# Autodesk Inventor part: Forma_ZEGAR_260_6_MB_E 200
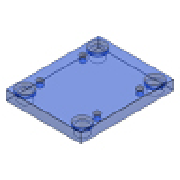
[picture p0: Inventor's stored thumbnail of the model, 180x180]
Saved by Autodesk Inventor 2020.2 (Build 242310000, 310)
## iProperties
Manager: www.cadconsulting.pl
Company: Fabian Stasiak CAD Consulting
Created: 2014-02
Part Number: Forma_ZEGAR_260_6_MB_E 200
Material: S 55 C
Description: Cavity Plate
Document SubType Name: Modeling
Designer: F.Stasiak
Standard Revision: 1
Manufacturer: DME
Language: pl-PL
Size Designation: 496x346x66
Categories: <MemberInstance><Categories><Category DisplayName="Forma wtryskowa" InternalName="349578f2-f4d4-4954-8c09-8e99297a61c0" Mnemonic="MOLD"><Category DisplayName="P
Density: 7.85 g/cm^3
Appearance: Clear - Blue
Catalog Web Link: www.expertbooks.pl
IsCustomPart: 1
Author: F.Stasiak
Subject: Zbiór ćwiczeń. Autodesk Inventor 2020. Kurs Professional
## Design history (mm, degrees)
sketch "Sketch1"
  geometry: L1 (-173, 248)-(173, 248); L2 (173, 248)-(173, -248); L3 (173, -248)-(-173, -248); L4 (-173, -248)-(-173, 248); 3 further points
  constraints: 8 end point, 2 midpoint, 2 parallel, 1 horizontal, 1 horizontal alignment, 1 perpendicular, 1 vertical alignment
  dimensions: "d126" = 346 distance between parallel lines of L2 L4 (= W_); "d127" = 496 distance between parallel lines of L3 L1 (= L)
extrude "Extrusion1" new body sketch "Sketch1" distance "d20" = 66 (= H_); taper "d30" = 0 deg
sketch "Sketch2"
  geometry: 3 further points
  dimensions: "d128" = 137 horizontal distance of point (0, 0) point (-137, 165) (= 0.5 x S1_W); "d129" = 165 vertical distance of point (0, 0) point (-137, 165) (= 0.5 x S1_L); "d130" = 208 vertical distance of point (0, 0) point (-137, 208) (= 0.5 x GP_L); "d131" = 137 horizontal distance of point (0, 0) point (-137, 208) (= 0.5 x GP_W)
hole "Hole1" sketch "Sketch2" diameter "d132" = 42 (= GP_d1); stored, may be unused: countersink angle "d136" = 90 deg, drill point angle "d138" = 0 deg; dims "d133" = 6, "d134" = 48 (= GP_d2), "d135" = 6 (= GP_k), "d137" = 66 (= H_)
pattern_linear "Rectangular Pattern1" dims "d148" = 416 (computed from GP_L, Nl), "d151" = 274 (computed from GP_W, Nw)
hole "Hole2" sketch "Sketch2" diameter "d139" = 13.835; stored, may be unused: countersink angle "d143" = 90 deg, drill point angle "d145" = 118 deg; dims "d140" = 24.5 (= H_l), "d141" = 48 (= GP_d2), "d142" = 6 (= GP_k), "d144" = 25 (= H_u)
pattern_linear "Rectangular Pattern2" dims "d154" = 330 (computed from S1_L, Ns), "d157" = 274 (computed from S1_W, Nw)
chamfer "Chamfer1" distance "d158" = 0.5; stored, may be unused: second distance "d159" = 2, angle "d160" = 45 deg
sketch "Szkic3"
  geometry: L1 (-78, -154.488)-(-78, 154.488); L2 (72.488, -160)-(-72.488, -160); L3 (78, 154.488)-(78, -154.488); L4 (-72.488, 160)-(72.488, 160); A1 r 4 centre (-75.879, 157.879) between (-72.488, 160) and (-78, 154.488); A2 r 4 centre (-75.879, -157.879) between (-78, -154.488) and (-72.488, -160); A3 r 4 centre (75.879, -157.879) between (72.488, -160) and (78, -154.488); A4 r 4 centre (75.879, 157.879) between (78, 154.488) and (72.488, 160)
  constraints: 8 end point, 8 point on circle, 4 centre point
extrude "Wyciągnięcie proste2" cut sketch "Szkic3" distance "d162" = 60; taper "d163" = 0 deg
node "Płaszczyzna konstrukcyjna2"
node "Płaszczyzna konstrukcyjna3"
node "Płaszczyzna konstrukcyjna4"
node "Płaszczyzna konstrukcyjna5"
node "Płaszczyzna konstrukcyjna6"
node "Płaszczyzna konstrukcyjna7"
node "Płaszczyzna konstrukcyjna8"
node "Płaszczyzna konstrukcyjna9"
feature "Rzeźbienie9"
feature "Rzeźbienie10"
feature "Rzeźbienie11"
feature "Rzeźbienie12"
feature "Rzeźbienie13"
feature "Rzeźbienie14"
feature "Rzeźbienie15"
feature "Rzeźbienie16"
feature "Rzeźbienie17"
feature "Rzeźbienie18"
feature "Rzeźbienie19"
feature "Rzeźbienie33"
feature "Gwint2" dims "d166" = 0, "d167" = 0
feature "Rzeźbienie34"
feature "Rzeźbienie36"
feature "Gwint4" dims "d170" = 0, "d171" = 0
feature "Rzeźbienie37"
feature "Gwint5" dims "d172" = 0, "d173" = 0
feature "Rzeźbienie38"
feature "Gwint6" dims "d174" = 0, "d175" = 0
feature "Rzeźbienie39"
feature "Gwint7" dims "d176" = 0, "d177" = 0
feature "Rzeźbienie40"
feature "Gwint8" dims "d178" = 0, "d179" = 0
feature "Rzeźbienie41"
feature "Gwint9" dims "d180" = 0, "d181" = 0
feature "Rzeźbienie42"
feature "Gwint10" dims "d182" = 0, "d183" = 0
feature "Rzeźbienie43"
feature "Gwint11" dims "d184" = 0, "d185" = 0
feature "Rzeźbienie44"
feature "Gwint12" dims "d186" = 0, "d187" = 0
feature "Rzeźbienie45"
feature "Gwint13" dims "d188" = 0, "d189" = 0
feature "Rzeźbienie46"
feature "Gwint14" dims "d190" = 0, "d191" = 0
feature "Rzeźbienie47"
feature "Rzeźbienie48"
feature "Rzeźbienie49"
feature "Rzeźbienie50"
feature "Rzeźbienie51"
feature "Rzeźbienie52"
feature "Rzeźbienie54"
feature "Rzeźbienie55"
feature "Rzeźbienie56"
feature "Rzeźbienie57"
feature "Rzeźbienie58"
feature "Rzeźbienie59"
feature "Rzeźbienie60"
feature "Rzeźbienie61"
feature "Rzeźbienie62"
feature "Rzeźbienie63"
feature "Rzeźbienie64"
feature "Rzeźbienie65"
feature "Rzeźbienie66"
feature "Rzeźbienie67"
feature "Rzeźbienie68"
feature "Rzeźbienie69"
feature "Rzeźbienie70"
body "Solid1"
feature "Powierzchnia9"
body "Srf9"
feature "Powierzchnia10"
body "Srf10"
feature "Powierzchnia11"
body "Srf11"
feature "Powierzchnia12"
body "Srf12"
feature "Powierzchnia13"
body "Srf13"
feature "Powierzchnia14"
body "Srf14"
feature "Powierzchnia15"
body "Srf15"
feature "Powierzchnia16"
body "Srf16"
feature "Powierzchnia17"
body "Srf17"
feature "Powierzchnia18"
body "Srf18"
feature "Powierzchnia19"
body "Srf19"
feature "Powierzchnia33"
body "Srf33"
feature "Powierzchnia34"
body "Srf34"
feature "Powierzchnia36"
body "Srf36"
feature "Powierzchnia37"
body "Srf37"
feature "Powierzchnia38"
body "Srf38"
feature "Powierzchnia39"
body "Srf39"
feature "Powierzchnia40"
body "Srf40"
feature "Powierzchnia41"
body "Srf41"
feature "Powierzchnia42"
body "Srf42"
feature "Powierzchnia43"
body "Srf43"
feature "Powierzchnia44"
body "Srf44"
feature "Powierzchnia45"
body "Srf45"
feature "Powierzchnia46"
body "Srf46"
feature "Powierzchnia47"
body "Srf47"
feature "Powierzchnia48"
body "Srf48"
feature "Powierzchnia49"
body "Srf49"
feature "Powierzchnia50"
body "Srf50"
feature "Powierzchnia51"
body "Srf51"
feature "Powierzchnia52"
body "Srf52"
feature "Powierzchnia54"
body "Srf54"
feature "Powierzchnia55"
body "Srf55"
feature "Powierzchnia56"
body "Srf56"
feature "Powierzchnia57"
body "Srf57"
feature "Powierzchnia58"
body "Srf58"
feature "Powierzchnia59"
body "Srf59"
feature "Powierzchnia60"
body "Srf60"
feature "Powierzchnia61"
body "Srf61"
feature "Powierzchnia62"
body "Srf62"
feature "Powierzchnia63"
body "Srf63"
feature "Powierzchnia64"
body "Srf64"
feature "Powierzchnia65"
body "Srf65"
feature "Powierzchnia66"
body "Srf66"
feature "Powierzchnia67"
body "Srf67"
feature "Powierzchnia68"
body "Srf68"
feature "Powierzchnia69"
body "Srf69"
feature "Powierzchnia70"
body "Srf70"
other parameters: "L" = 496 [user parameter; used in 1 equation term], "W_" = 346 [user parameter; used in 1 equation term], "H_" = 66 [user parameter; used in 2 equation terms], "GP_W" = 274 [user parameter; used in 2 equation terms], "GP_d1" = 42 [user parameter; used in 1 equation term], "GP_d2" = 48 [user parameter; used in 2 equation terms], "GP_k" = 6 [user parameter; used in 2 equation terms], "S1_W" = 274 [user parameter; used in 2 equation terms], "GP_L" = 416 [user parameter; used in 2 equation terms], "H_u" = 25 [user parameter; used in 1 equation term], "H_l" = 24.5 [user parameter; used in 1 equation term], "d161" = -20.1915, "d192" = 39, "d194" = 9.8085, "d195" = 0, "d196" = 0, "d197" = 0, "d198" = 39, "d200" = 9.8085, "d201" = 0, "d202" = 0, "d203" = -180 deg, "d204" = -39, "d206" = 9.8085, "d207" = 0, "d208" = 0, "d209" = 0, "d210" = -39, "d212" = 9.8085, "d213" = 0, "d214" = 0, "d215" = -180 deg, "d216" = 0, "d217" = 0, "d218" = 9.8085, "d219" = 0, "d220" = 0, "d221" = 0
